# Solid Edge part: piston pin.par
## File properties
Author: Robert a Rhodes jr
Template: Normal.par
Last saved by: Cadcim
Revision: 6
Application: Solid Edge
Accuracy: 0.99
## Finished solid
Body 1: solid body, 4 faces, 4 edges, 0 vertices.
  Faces by surface: cylinder 2, plane 2
  Edges by curve: circle 4
Bounding box of the edges (mm): 22.000 x 22.000 x 80.000, from (-11, -11, -80) to (11, 11, 0).
Cylindrical faces by radius (mm): R5.5 x1, R11 x1
Planar faces by outward normal: +z 1, -z 1
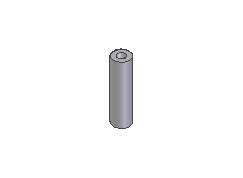
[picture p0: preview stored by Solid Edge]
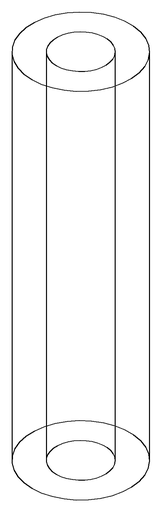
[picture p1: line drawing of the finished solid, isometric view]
